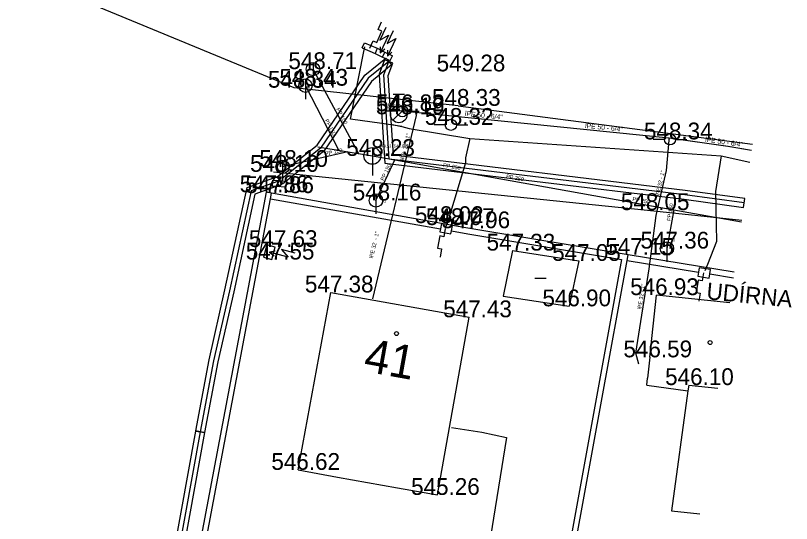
# Model space of a CAD drawing. Extents: x -669995 to -669686, y -1125551 to -1125263.
# Drawn here: x -669725.33 to -669690.66, y -1125362.29 to -1125339.58 of the extents above; entities that cross this region are included whole.
import ezdxf

# ---------------------------------------------------------------- set-up
doc = ezdxf.new("R2010")
doc.units = 0
for name, color, linetype in [('G_Bod_tecka', 7, 'Continuous'), ('G_Bod_vyska', 7, 'Continuous'), ('G_Breh_Teren', 7, 'Continuous'), ('G_Budovy-znacky', 7, 'Continuous'), ('G_Budovy_Objekty', 7, 'Continuous'), ('G_Budovy_vstupy', 7, 'Continuous'), ('G_Cisla_popisna', 7, 'Continuous'), ('G_Plochy_zpevnene', 7, 'Continuous'), ('G_Ploty', 7, 'Continuous'), ('G_Poznamky_odkaz', 7, 'Continuous'), ('G_Site-kanalizace', 7, 'Continuous'), ('G_Site-Rozvadece', 7, 'Continuous'), ('G_Site-vodovod', 7, 'Continuous'), ('G_Z_CHRANICKA-TEPLOVOD_kotovane', 7, 'Continuous'), ('G_Z_ELsilove_podz_kotovane', 7, 'Continuous'), ('G_Z_KANAL_podz_kotovane', 7, 'Continuous'), ('G_Z_PLYNY_podz_geodeticky', 7, 'Continuous'), ('G_Z_SPOJE_podz_geodeticky', 7, 'Continuous'), ('G_Z_SPOJE_podz_kotovane', 7, 'Continuous'), ('G_Z_SPOJE_podz_priblizne', 7, 'Continuous'), ('G_Z_VODA_podz_kotovane', 7, 'Continuous'), ('Vrstva 11', 7, 'Continuous'), ('Vrstva 2', 7, 'Continuous'), ('Vrstva 25', 7, 'Continuous'), ('Vrstva 26', 7, 'Continuous'), ('Vrstva 3', 7, 'Continuous'), ('Vrstva 4', 7, 'Continuous'), ('Vrstva 6', 7, 'Continuous'), ('Vrstva 7', 7, 'Continuous'), ('Vrstva 8', 7, 'Continuous')]:
    doc.layers.add(name, color=color, linetype=linetype)

msp = doc.modelspace()

# ---------------------------------------------------------------- linework, layer by layer
at = {"layer": 'G_Bod_tecka'}
for p, q in [((-669712.04, -1125341.98), (-669712.04, -1125341.98)), ((-669705.35, -1125342.08), (-669705.35, -1125342.08)), ((-669712.89, -1125342.81), (-669712.89, -1125342.81)), ((-669712.38, -1125342.72), (-669712.38, -1125342.72)), ((-669708.05, -1125343.86), (-669708.05, -1125343.86)), ((-669705.56, -1125343.62), (-669705.56, -1125343.62)), ((-669708.21, -1125344), (-669708.21, -1125344)), ((-669705.88, -1125344.47), (-669705.88, -1125344.47)), ((-669696.09, -1125345.12), (-669696.09, -1125345.12)), ((-669709.39, -1125345.86), (-669709.39, -1125345.86)), ((-669713.4, -1125346.35), (-669713.4, -1125346.35)), ((-669713.81, -1125346.57), (-669713.81, -1125346.57)), ((-669714.14, -1125347.48), (-669714.14, -1125347.48)), ((-669713.89, -1125347.52), (-669713.89, -1125347.52)), ((-669709.23, -1125347.85), (-669709.23, -1125347.85)), ((-669697.1, -1125348.28), (-669697.1, -1125348.28)), ((-669706.3, -1125348.86), (-669706.3, -1125348.86)), ((-669705.81, -1125348.95), (-669705.81, -1125348.95)), ((-669705.12, -1125349.09), (-669705.12, -1125349.09)), ((-669713.73, -1125349.93), (-669713.73, -1125349.93)), ((-669703.12, -1125350.09), (-669703.12, -1125350.09)), ((-669696.23, -1125350), (-669696.23, -1125350)), ((-669713.88, -1125350.49), (-669713.88, -1125350.49)), ((-669700.17, -1125350.55), (-669700.17, -1125350.55)), ((-669697.96, -1125350.28), (-669697.96, -1125350.28)), ((-669711.24, -1125351.96), (-669711.24, -1125351.96)), ((-669696.69, -1125352.08), (-669696.69, -1125352.08)), ((-669700.59, -1125352.58), (-669700.59, -1125352.58)), ((-669705.06, -1125353.07), (-669705.06, -1125353.07)), ((-669696.99, -1125354.86), (-669696.99, -1125354.86)), ((-669695.25, -1125356.1), (-669695.25, -1125356.1)), ((-669712.71, -1125359.89), (-669712.71, -1125359.89)), ((-669706.48, -1125361.01), (-669706.48, -1125361.01))]:
    msp.add_line(p, q, dxfattribs=at)
at = {"layer": 'G_Breh_Teren'}
msp.add_line((-669712.89, -1125342.81), (-669721.76, -1125339.15), dxfattribs=at)
at = {"layer": 'G_Budovy-znacky'}
msp.add_line((-669702.13, -1125351.33), (-669701.63, -1125351.33), dxfattribs=at)
for centre in [(-669708.31, -1125353.8), (-669694.3, -1125354.2)]:
    msp.add_circle(centre, 0.0875, dxfattribs=at)
at = {"layer": 'G_Budovy_Objekty'}
for p, q in [((-669703.12, -1125350.09), (-669703.54, -1125352.12)), ((-669703.12, -1125350.09), (-669700.17, -1125350.55)), ((-669700.17, -1125350.55), (-669700.59, -1125352.58)), ((-669712.71, -1125359.89), (-669711.24, -1125351.96)), ((-669711.24, -1125351.96), (-669705.06, -1125353.07)), ((-669703.54, -1125352.12), (-669700.59, -1125352.58)), ((-669696.99, -1125354.86), (-669696.69, -1125352.08)), ((-669693.412, -1125352.428), (-669696.69, -1125352.08)), ((-669706.48, -1125361.01), (-669705.06, -1125353.07)), ((-669697.12, -1125356.11), (-669697.09, -1125355.79)), ((-669695.25, -1125356.1), (-669695.29, -1125356.36)), ((-669695.25, -1125356.1), (-669693.955, -1125356.243)), ((-669697.12, -1125356.11), (-669695.29, -1125356.36)), ((-669695.29, -1125356.36), (-669696.03, -1125361.72)), ((-669712.71, -1125359.89), (-669710.94, -1125360.21)), ((-669708.26, -1125360.69), (-669706.48, -1125361.01)), ((-669696.03, -1125361.72), (-669694.754, -1125361.859))]:
    msp.add_line(p, q, dxfattribs=at)
at = {"layer": 'G_Budovy_vstupy'}
for p, q in [((-669696.99, -1125354.86), (-669697.09, -1125355.79)), ((-669710.94, -1125360.21), (-669708.26, -1125360.69))]:
    msp.add_line(p, q, dxfattribs=at)
at = {"layer": 'G_Plochy_zpevnene'}
for points in [[(-669705.56, -1125343.62), (-669712.89, -1125342.81)], [(-669705.56, -1125343.62), (-669692.403, -1125345.341)], [(-669713.81, -1125346.57), (-669697.1, -1125348.28)], [(-669697.1, -1125348.28), (-669692.884, -1125348.724)]]:
    msp.add_lwpolyline(points, dxfattribs=at)
at = {"layer": 'G_Ploty'}
for p, q in [((-669714.14, -1125347.48), (-669718.58, -1125370.99)), ((-669718.33, -1125371.04), (-669713.94, -1125347.77)), ((-669713.89, -1125347.52), (-669714.14, -1125347.48)), ((-669713.94, -1125347.77), (-669713.89, -1125347.52)), ((-669713.94, -1125347.77), (-669706.35, -1125349.12)), ((-669706.3, -1125348.88), (-669713.89, -1125347.52)), ((-669705.12, -1125349.09), (-669705.81, -1125348.97)), ((-669697.96, -1125350.28), (-669705.12, -1125349.09)), ((-669705.86, -1125349.21), (-669705.12, -1125349.34)), ((-669705.12, -1125349.34), (-669698.25, -1125350.49)), ((-669698.25, -1125350.49), (-669702.58, -1125374.27)), ((-669702.29, -1125374.04), (-669698, -1125350.53)), ((-669698, -1125350.53), (-669697.96, -1125350.28)), ((-669698, -1125350.53), (-669694.81, -1125351.05)), ((-669693.216, -1125351.054), (-669697.96, -1125350.28)), ((-669694.31, -1125351.13), (-669693.251, -1125351.302))]:
    msp.add_line(p, q, dxfattribs=at)
at = {"layer": 'G_Site-kanalizace'}
for p, q in [((-669712.04, -1125341.68), (-669712.04, -1125342.58)), ((-669712.38, -1125342.42), (-669712.38, -1125343.32)), ((-669709.39, -1125345.485), (-669709.39, -1125346.735)), ((-669713.4, -1125346.05), (-669713.4, -1125346.95)), ((-669709.23, -1125347.55), (-669709.23, -1125348.45)), ((-669696.23, -1125349.7), (-669696.23, -1125350.6))]:
    msp.add_line(p, q, dxfattribs=at)
for centre, radius in [((-669712.04, -1125341.98), 0.3), ((-669712.38, -1125342.72), 0.3), ((-669709.39, -1125345.86), 0.375), ((-669713.4, -1125346.35), 0.3), ((-669709.23, -1125347.85), 0.3), ((-669696.23, -1125350), 0.3)]:
    msp.add_circle(centre, radius, dxfattribs=at)
at = {"layer": 'G_Site-Rozvadece'}
for p, q in [((-669708.78, -1125340.126), (-669709.05, -1125340.691)), ((-669709.05, -1125340.691), (-669708.662, -1125340.46)), ((-669708.662, -1125340.46), (-669709.04, -1125341.25)), ((-669708.46, -1125340.276), (-669708.73, -1125340.841)), ((-669709.84, -1125341.03), (-669709.74, -1125340.8)), ((-669709.74, -1125340.8), (-669709.17, -1125341.05)), ((-669708.73, -1125340.841), (-669708.342, -1125340.61)), ((-669708.342, -1125340.61), (-669708.72, -1125341.4)), ((-669709.84, -1125341.03), (-669709.27, -1125341.28)), ((-669709.17, -1125341.05), (-669709.27, -1125341.28)), ((-669709.033, -1125340.981), (-669709.04, -1125341.25)), ((-669709.04, -1125341.25), (-669708.835, -1125341.076)), ((-669708.713, -1125341.131), (-669708.72, -1125341.4)), ((-669708.94, -1125341.44), (-669708.83, -1125341.22)), ((-669708.72, -1125341.4), (-669708.515, -1125341.226)), ((-669708.6, -1125341.6), (-669708.49, -1125341.38)), ((-669713.725, -1125350.117), (-669713.991, -1125350.16)), ((-669713.145, -1125350.386), (-669713.991, -1125350.16)), ((-669713.991, -1125350.16), (-669713.783, -1125350.329)), ((-669712.839, -1125350.209), (-669713.443, -1125350.047)), ((-669713.443, -1125350.047), (-669713.145, -1125350.386))]:
    msp.add_line(p, q, dxfattribs=at)
for points in [[(-669709.5, -1125341.05), (-669709.351, -1125340.713), (-669709.184, -1125340.787), (-669708.962, -1125340.281), (-669709.129, -1125340.207), (-669708.982, -1125339.869)], [(-669709.17, -1125341.05), (-669708.83, -1125341.22), (-669708.49, -1125341.38)], [(-669709.27, -1125341.28), (-669708.94, -1125341.44), (-669708.6, -1125341.6)], [(-669706.13, -1125349.11), (-669706.198, -1125349.471), (-669706.378, -1125349.438), (-669706.478, -1125349.981), (-669706.298, -1125350.015), (-669706.363, -1125350.377)], [(-669694.59, -1125351.081), (-669694.649, -1125351.445), (-669694.83, -1125351.415), (-669694.917, -1125351.961), (-669694.737, -1125351.991), (-669694.794, -1125352.353)]]:
    msp.add_lwpolyline(points, dxfattribs=at)
for points in [[(-669706.3, -1125348.88), (-669706.35, -1125349.12), (-669706.37, -1125349.25), (-669705.88, -1125349.34), (-669705.86, -1125349.21), (-669705.81, -1125348.97)], [(-669714.1, -1125349.83), (-669714.25, -1125350.39), (-669713.88, -1125350.49), (-669713.73, -1125349.93)], [(-669694.78, -1125350.86), (-669694.81, -1125351.05), (-669694.84, -1125351.24), (-669694.34, -1125351.32), (-669694.31, -1125351.13), (-669694.28, -1125350.94)]]:
    msp.add_lwpolyline(points, close=True, dxfattribs=at)
at = {"layer": 'G_Site-vodovod'}
for p, q in [((-669708.46, -1125343.1), (-669707.96, -1125343.1)), ((-669708.21, -1125343.625), (-669708.21, -1125343.1)), ((-669708.3, -1125343.86), (-669708.8, -1125343.86)), ((-669708.475, -1125344.265), (-669707.945, -1125343.735)), ((-669707.8, -1125343.86), (-669707.3, -1125343.86)), ((-669706.13, -1125344.47), (-669706.63, -1125344.47)), ((-669705.63, -1125344.47), (-669705.13, -1125344.47)), ((-669696.34, -1125345.12), (-669696.84, -1125345.12)), ((-669695.84, -1125345.12), (-669695.34, -1125345.12))]:
    msp.add_line(p, q, dxfattribs=at)
for centre, radius in [((-669708.05, -1125343.86), 0.25), ((-669708.21, -1125344), 0.375), ((-669705.88, -1125344.47), 0.25), ((-669696.09, -1125345.12), 0.25)]:
    msp.add_circle(centre, radius, dxfattribs=at)
at = {"layer": 'G_Z_CHRANICKA-TEPLOVOD_kotovane'}
msp.add_line((-669692.804, -1125348.161), (-669692.748, -1125347.766), dxfattribs=at)
for points in [[(-669713.629, -1125346.783), (-669711.858, -1125345.372), (-669709.719, -1125342.254), (-669708.787, -1125341.486), (-669708.66, -1125341.64), (-669708.533, -1125341.794), (-669709.08, -1125342.245), (-669709.421, -1125342.526), (-669711.562, -1125345.648), (-669713.236, -1125346.981), (-669713.405, -1125347.116), (-669713.53, -1125346.96), (-669713.53, -1125346.96), (-669713.655, -1125346.804)], [(-669713.629, -1125346.783), (-669713.598, -1125346.772), (-669713.53, -1125346.96), (-669713.53, -1125346.96), (-669713.462, -1125347.148), (-669713.69, -1125347.23), (-669714.638, -1125347.571), (-669715.585, -1125351.933), (-669716.294, -1125355.06), (-669716.883, -1125358.226), (-669716.883, -1125358.227), (-669717.078, -1125358.19), (-669717.277, -1125358.153), (-669716.686, -1125354.98), (-669715.975, -1125351.847), (-669714.982, -1125347.269)], [(-669713.69, -1125347.23), (-669713.849, -1125347.219), (-669713.829, -1125346.939), (-669713.53, -1125346.96), (-669713.236, -1125346.981), (-669713.231, -1125346.981), (-669713.251, -1125347.261)], [(-669725.327, -1125392.473), (-669724.624, -1125389.742), (-669722.972, -1125382.821), (-669720.904, -1125377.309), (-669720.146, -1125372.532), (-669718.876, -1125366.96), (-669717.277, -1125358.154), (-669717.078, -1125358.19), (-669716.883, -1125358.226), (-669716.883, -1125358.227), (-669718.484, -1125367.04), (-669719.754, -1125372.608), (-669720.516, -1125377.411), (-669722.588, -1125382.939), (-669724.236, -1125389.838), (-669724.946, -1125392.6), (-669725.14, -1125392.55), (-669725.334, -1125392.5)]]:
    msp.add_lwpolyline(points, close=True, dxfattribs=at)
msp.add_lwpolyline([(-669692.748, -1125347.766), (-669695.405, -1125347.402), (-669708.451, -1125345.831), (-669708.678, -1125342.26), (-669708.473, -1125341.71), (-669708.66, -1125341.64), (-669708.847, -1125341.57), (-669709.082, -1125342.2), (-669709.08, -1125342.245), (-669708.829, -1125346.189), (-669695.455, -1125347.798), (-669692.804, -1125348.161)], dxfattribs=at)
at = {"layer": 'G_Z_ELsilove_podz_kotovane'}
for points in [[(-669692.776, -1125347.963), (-669695.43, -1125347.6), (-669708.64, -1125346.01), (-669708.88, -1125342.23), (-669708.66, -1125341.64), (-669709.57, -1125342.39), (-669711.71, -1125345.51), (-669713.424, -1125346.875), (-669713.438, -1125347.078), (-669713.55, -1125347.24)], [(-669713.55, -1125347.24), (-669713.633, -1125346.997), (-669714.81, -1125347.42), (-669715.78, -1125351.89), (-669716.49, -1125355.02), (-669717.08, -1125358.19), (-669717.768, -1125361.979), (-669718.68, -1125367), (-669719.95, -1125372.57), (-669720.71, -1125377.36), (-669722.78, -1125382.88)]]:
    msp.add_lwpolyline(points, dxfattribs=at)
at = {"layer": 'G_Z_KANAL_podz_kotovane'}
for p, q in [((-669710, -1125345.76), (-669712.04, -1125341.98)), ((-669710.48, -1125345.68), (-669713.4, -1125346.35)), ((-669709.23, -1125347.85), (-669708.38, -1125346.04)), ((-669695.92, -1125348.27), (-669696.23, -1125350))]:
    msp.add_line(p, q, dxfattribs=at)
for points in [[(-669712.38, -1125342.72), (-669710.89, -1125345.61), (-669710.89, -1125345.61)], [(-669711.82, -1125345.46), (-669709.39, -1125345.86), (-669708.38, -1125346.04), (-669695.92, -1125348.27), (-669692.897, -1125348.812)]]:
    msp.add_lwpolyline(points, dxfattribs=at)
at = {"layer": 'G_Z_PLYNY_podz_geodeticky'}
for points in [[(-669708.07, -1125344.55), (-669708.97, -1125344.41), (-669710.37, -1125344.22), (-669709.77, -1125341.19), (-669709.73, -1125340.99)], [(-669708.5, -1125344.45), (-669708.07, -1125344.55), (-669707.74, -1125344.64), (-669705.03, -1125345.08), (-669693.81, -1125345.86), (-669692.517, -1125346.143)], [(-669705.03, -1125345.08), (-669705.22, -1125345.94), (-669705.22, -1125346.17), (-669705.99, -1125348.68), (-669706.12, -1125349.06)], [(-669693.81, -1125345.86), (-669694.05, -1125347.45), (-669694.01, -1125349.68), (-669694.41, -1125350.71), (-669694.53, -1125350.99)]]:
    msp.add_lwpolyline(points, dxfattribs=at)
at = {"layer": 'G_Z_SPOJE_podz_geodeticky'}
msp.add_lwpolyline([(-669705.85, -1125358), (-669704.5, -1125358.21), (-669703.4, -1125358.44), (-669704.18, -1125363.34), (-669702.86, -1125373.47), (-669703.46, -1125378.8), (-669703.26, -1125379.33), (-669702.98, -1125379.87), (-669697.457, -1125380.845)], dxfattribs=at)
at = {"layer": 'G_Z_SPOJE_podz_kotovane'}
msp.add_lwpolyline([(-669705.85, -1125358), (-669704.5, -1125358.21), (-669703.4, -1125358.44), (-669704.18, -1125363.34), (-669702.86, -1125373.47), (-669703.46, -1125378.8), (-669703.26, -1125379.33), (-669702.98, -1125379.87), (-669697.457, -1125380.845)], dxfattribs=at)
at = {"layer": 'G_Z_SPOJE_podz_priblizne'}
msp.add_lwpolyline([(-669705.85, -1125358), (-669704.5, -1125358.21), (-669703.4, -1125358.44), (-669704.18, -1125363.34), (-669702.86, -1125373.47), (-669703.46, -1125378.8), (-669703.26, -1125379.33), (-669702.98, -1125379.87), (-669697.457, -1125380.845)], dxfattribs=at)
at = {"layer": 'G_Z_VODA_podz_kotovane'}
for points in [[(-669707.46, -1125343.92), (-669707.43, -1125344.06), (-669709.38, -1125352.25)], [(-669707.84, -1125343.88), (-669708.05, -1125343.86), (-669708.28, -1125343.84)], [(-669692.442, -1125345.618), (-669693.5, -1125345.44), (-669696.13, -1125345.06), (-669707.46, -1125343.92), (-669707.46, -1125343.92), (-669707.84, -1125343.88)], [(-669697.48, -1125355.17), (-669697.62, -1125354.67), (-669697.02, -1125350.9), (-669696.71, -1125348.52), (-669696.25, -1125346.51), (-669696.12, -1125345.16), (-669696.13, -1125345.06)]]:
    msp.add_lwpolyline(points, dxfattribs=at)
at = {"layer": 'Vrstva 11'}
for p, q in [((-669710, -1125345.76), (-669712.04, -1125341.98)), ((-669710.48, -1125345.68), (-669713.4, -1125346.35)), ((-669709.23, -1125347.85), (-669708.38, -1125346.04)), ((-669695.92, -1125348.27), (-669696.23, -1125350))]:
    msp.add_line(p, q, dxfattribs=at)
for points in [[(-669712.38, -1125342.72), (-669710.89, -1125345.61), (-669710.888, -1125345.613)], [(-669711.82, -1125345.46), (-669709.39, -1125345.86), (-669708.38, -1125346.04), (-669695.92, -1125348.27), (-669692.897, -1125348.812)]]:
    msp.add_lwpolyline(points, dxfattribs=at)
at = {"layer": 'Vrstva 25'}
for points in [[(-669707.464, -1125343.919), (-669707.434, -1125344.057), (-669709.379, -1125352.247)], [(-669707.843, -1125343.881), (-669708.05, -1125343.86), (-669708.28, -1125343.84)]]:
    msp.add_lwpolyline(points, dxfattribs=at)
at = {"layer": 'Vrstva 26'}
for points in [[(-669692.442, -1125345.616), (-669693.496, -1125345.439), (-669696.13, -1125345.06), (-669707.463, -1125343.919), (-669707.464, -1125343.919), (-669707.843, -1125343.881)], [(-669697.48, -1125355.17), (-669697.62, -1125354.67), (-669697.02, -1125350.9), (-669696.71, -1125348.52), (-669696.25, -1125346.51), (-669696.12, -1125345.16), (-669696.13, -1125345.06)]]:
    msp.add_lwpolyline(points, dxfattribs=at)
at = {"layer": 'Vrstva 6'}
for p, q in [((-669708.05, -1125343.86), (-669708.05, -1125343.86)), ((-669707.434, -1125344.057), (-669707.434, -1125344.057)), ((-669696.12, -1125345.16), (-669696.12, -1125345.16))]:
    msp.add_line(p, q, dxfattribs=at)
at = {"layer": 'Vrstva 7'}
msp.add_line((-669708.28, -1125343.84), (-669708.28, -1125343.84), dxfattribs=at)
at = {"layer": 'Vrstva 8'}
for p, q in [((-669712.04, -1125341.98), (-669712.04, -1125341.98)), ((-669712.38, -1125342.72), (-669712.38, -1125342.72)), ((-669709.51, -1125345.84), (-669709.51, -1125345.84)), ((-669713.4, -1125346.35), (-669713.4, -1125346.35)), ((-669709.23, -1125347.85), (-669709.23, -1125347.85)), ((-669696.23, -1125350), (-669696.23, -1125350))]:
    msp.add_line(p, q, dxfattribs=at)

# ---------------------------------------------------------------- texts
at = {"layer": 'G_Bod_vyska'}
for s, p in [('548.71', (-669713.142, -1125341.98)), ('549.28', (-669706.516, -1125342.08)), ('548.34', (-669714.054, -1125342.81)), ('548.43', (-669713.544, -1125342.72)), ('548.33', (-669706.724, -1125343.62)), ('548.19', (-669709.234, -1125344)), ('546.82', (-669709.228, -1125343.86)), ('548.32', (-669707.044, -1125344.47)), ('548.34', (-669697.254, -1125345.12)), ('548.23', (-669710.554, -1125345.86)), ('548.10', (-669714.441, -1125346.35)), ('548.10', (-669714.854, -1125346.57)), ('547.86', (-669715.318, -1125347.48)), ('547.86', (-669715.068, -1125347.52)), ('548.16', (-669710.266, -1125347.85)), ('548.05', (-669698.286, -1125348.28)), ('548.02', (-669707.486, -1125348.86)), ('548.07', (-669706.996, -1125348.95)), ('547.96', (-669706.3, -1125349.09)), ('547.63', (-669714.908, -1125349.93)), ('547.33', (-669704.284, -1125350.09)), ('547.36', (-669697.408, -1125350)), ('547.55', (-669715.044, -1125350.49)), ('547.05', (-669701.356, -1125350.55)), ('547.15', (-669698.98, -1125350.28)), ('547.38', (-669712.404, -1125351.96)), ('546.93', (-669697.87, -1125352.08)), ('546.90', (-669701.791, -1125352.58)), ('547.43', (-669706.224, -1125353.07)), ('546.59', (-669698.17, -1125354.86)), ('546.10', (-669696.308, -1125356.1)), ('546.62', (-669713.902, -1125359.89)), ('545.26', (-669707.658, -1125361.01))]:
    msp.add_text(s, height=0.75, dxfattribs=at).set_placement(p)
at = {"layer": 'G_Cisla_popisna'}
msp.add_text('41', height=1.5, rotation=349.8176, dxfattribs=at).set_placement((-669709.827, -1125355.477))
at = {"layer": 'G_Poznamky_odkaz'}
msp.add_text('UDÍRNA', height=0.75, rotation=354.41, dxfattribs=at).set_placement((-669694.486, -1125352.262))
at = {"layer": 'Vrstva 2'}
for s, height, p in [('\xa0()', 0.1316, (-669711.835, -1125341.627)), ('\xa0()', 0.1316, (-669712.605, -1125342.368)), ('548.23 (545.88)', 0.13163, (-669709.097, -1125345.488)), ('\xa0()', 0.1316, (-669713.195, -1125345.997)), ('\xa0()', 0.1316, (-669708.954, -1125347.927)), ('\xa0()', 0.1316, (-669696.025, -1125349.647))]:
    msp.add_text(s, height=height, dxfattribs=at).set_placement(p)
at = {"layer": 'Vrstva 3'}
for s, rotation, p in [('PP 150', 298.3342, (-669711.015, -1125343.768)), ('PP 150', 297.3019, (-669711.524, -1125344.268)), ('PP 150', 12.9174, (-669711.481, -1125345.855)), ('PP 150', 64.7989, (-669708.881, -1125346.984)), ('PP 250', 349.8942, (-669706.244, -1125346.351)), ('PP 250', 349.8463, (-669703.424, -1125346.855)), ('PP 250', 349.8942, (-669697.781, -1125347.866)), ('PP 150', 79.8131, (-669696.065, -1125348.78))]:
    msp.add_text(s, height=0.1755, rotation=rotation, dxfattribs=at).set_placement(p)
at = {"layer": 'Vrstva 4'}
for s, height, rotation, p in [('LT 80', 0.2194, 354.6806, (-669708.731, -1125343.726)), ('lPE 50 - 6/4"', 0.21938, 354.2287, (-669705.261, -1125344.07)), ('lPE 50 - 6/4"', 0.21938, 354.2305, (-669699.892, -1125344.61)), ('lPE  32 - 1"', 0.17551, 76.7, (-669707.975, -1125346.073)), ('lPE 50 - 6/4"', 0.21938, 351.8191, (-669694.529, -1125345.22)), ('lPE 32 - 1"', 0.17551, 77.1647, (-669696.577, -1125347.663)), ('lPE 32  - 1"', 0.17551, 76.6331, (-669709.365, -1125350.449)), ('lPE 32 - 1"', 0.17551, 81.0372, (-669697.374, -1125352.727))]:
    msp.add_text(s, height=height, rotation=rotation, dxfattribs=at).set_placement(p)

doc.saveas('drawing.dxf')
